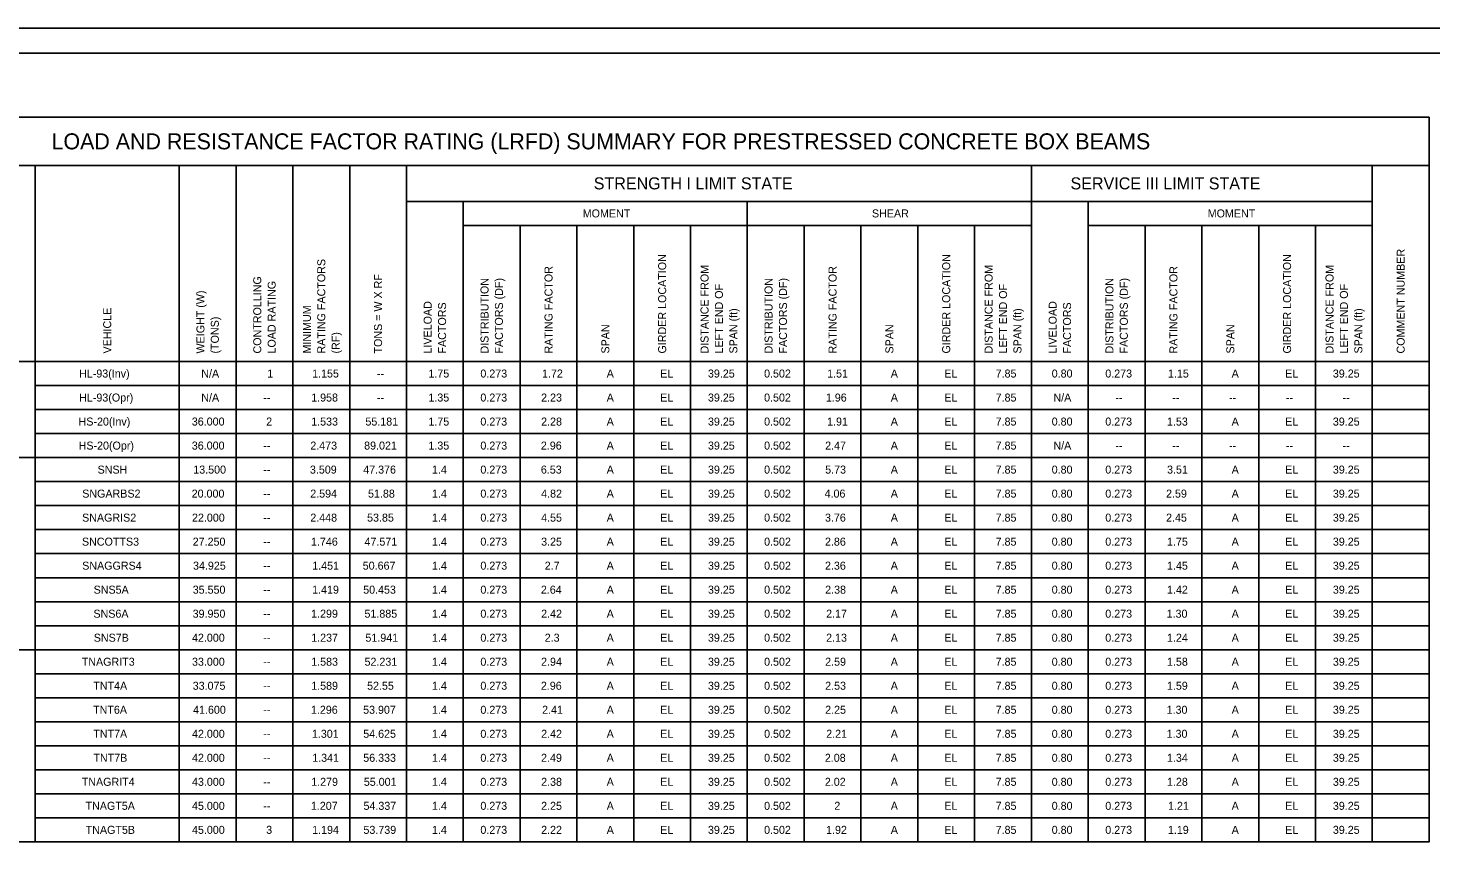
# Model space of a CAD drawing. Extents: x -190 to 360, y 729 to 1065.
# Drawn here: x 7.6 to 226.8, y 820.2 to 949.5 of the extents above; entities that cross this region are included whole.
import ezdxf

# ---------------------------------------------------------------- set-up
doc = ezdxf.new("R2010")
doc.units = 0
for name, color, linetype in [('Bill of Material Border Lines', 7, 'Continuous'), ('Bill of Material Lines', 7, 'Continuous'), ('Miscellaneous Lines', 7, 'Continuous'), ('Plan Sheet CELL', 7, 'Continuous'), ('Plot Shape CELL', 7, 'Continuous'), ('Text', 7, 'Continuous')]:
    doc.layers.add(name, color=color, linetype=linetype)

msp = doc.modelspace()

# ---------------------------------------------------------------- linework, layer by layer
at = {"layer": 'Bill of Material Border Lines'}
msp.add_lwpolyline([(-9.99, 935.55), (226.51, 935.55), (226.51, 822.42), (-9.99, 822.42), (-9.99, 935.55)], dxfattribs=at)
at = {"layer": 'Bill of Material Lines'}
for p, q in [((-9.99, 928.05), (226.51, 928.05)), ((8.76, 928.05), (8.76, 822.42)), ((31.26, 928.05), (31.26, 822.42)), ((40.14, 928.05), (40.14, 822.42)), ((49.01, 928.05), (49.01, 822.42)), ((57.89, 928.05), (57.89, 822.42)), ((66.76, 928.05), (66.76, 822.42)), ((164.39, 928.05), (164.39, 822.42)), ((217.64, 928.05), (217.64, 822.42)), ((226.51, 928.05), (226.51, 822.42)), ((66.76, 922.42), (217.64, 922.42)), ((75.64, 922.42), (75.64, 822.42)), ((120.01, 922.42), (120.01, 822.42)), ((173.26, 922.42), (173.26, 822.42)), ((75.64, 918.67), (164.39, 918.67)), ((84.51, 918.67), (84.51, 822.42)), ((93.39, 918.67), (93.39, 822.42)), ((102.26, 918.67), (102.26, 822.42)), ((111.14, 918.67), (111.14, 822.42)), ((128.89, 918.67), (128.89, 822.42)), ((137.76, 918.67), (137.76, 822.42)), ((146.64, 918.67), (146.64, 822.42)), ((155.51, 918.67), (155.51, 822.42)), ((173.26, 918.67), (217.64, 918.67)), ((182.14, 918.67), (182.14, 822.42)), ((191.01, 918.67), (191.01, 822.42)), ((199.89, 918.67), (199.89, 822.42)), ((208.76, 918.67), (208.76, 822.42)), ((-9.99, 897.42), (226.51, 897.42)), ((8.76, 893.67), (226.51, 893.67)), ((8.76, 889.92), (226.51, 889.92)), ((8.76, 886.17), (226.51, 886.17)), ((-9.99, 882.42), (226.51, 882.42)), ((8.76, 878.67), (226.51, 878.67)), ((8.76, 874.92), (226.51, 874.92)), ((8.76, 871.17), (226.51, 871.17)), ((8.76, 867.42), (226.51, 867.42)), ((8.76, 863.67), (226.51, 863.67)), ((8.76, 859.92), (226.51, 859.92)), ((8.76, 856.17), (226.51, 856.17)), ((2.64, 852.42), (226.51, 852.42)), ((8.76, 848.67), (226.51, 848.67)), ((8.76, 844.92), (226.51, 844.92)), ((8.76, 841.17), (226.51, 841.17)), ((8.76, 837.42), (226.51, 837.42)), ((8.76, 833.67), (226.51, 833.67)), ((8.76, 829.92), (226.51, 829.92)), ((8.76, 826.17), (226.51, 826.17))]:
    msp.add_line(p, q, dxfattribs=at)
at = {"layer": 'Plan Sheet CELL'}
msp.add_line((-16.76, 945.55), (303.24, 945.55), dxfattribs=at)
at = {"layer": 'Plot Shape CELL'}
msp.add_lwpolyline([(-27.3, 949.49), (303.33, 949.49), (303.33, 729.49), (-27.3, 729.49)], close=True, dxfattribs=at)

# ---------------------------------------------------------------- texts
at = {"layer": 'Miscellaneous Lines'}
for s, p in [('1', (45.01, 894.92)), ('1.15', (185.72, 894.92)), ('39.25', (211.48, 894.92)), ('2', (44.85, 887.42)), ('1.53', (185.57, 887.42)), ('39.25', (211.48, 887.42)), ('3', (44.85, 823.67)), ('1.19', (185.71, 823.67)), ('39.25', (211.48, 823.67))]:
    msp.add_text(s, height=1.25, dxfattribs=at).set_placement(p)
at = {"layer": 'Text'}
for s, height, p in [('LOAD AND RESISTANCE FACTOR RATING (LRFD) SUMMARY FOR PRESTRESSED CONCRETE BOX BEAMS', 2.5, (11.32, 930.55)), ('STRENGTH I LIMIT STATE', 1.875, (96.02, 924.3)), ('SERVICE III LIMIT STATE', 1.875, (170.5, 924.3)), ('MOMENT', 1.25, (94.3, 919.92)), ('SHEAR', 1.25, (139.48, 919.92)), ('MOMENT', 1.25, (191.93, 919.92)), ('HL-93(Inv)', 1.25, (15.62, 894.92)), ('N/A', 1.25, (34.71, 894.92)), ('1.155', 1.25, (52.03, 894.92)), ('--', 1.25, (62.14, 894.92)), ('1.75', 1.25, (70.19, 894.92)), ('0.273', 1.25, (78.31, 894.92)), ('1.72', 1.25, (87.94, 894.92)), ('A', 1.25, (98.04, 894.92)), ('EL', 1.25, (106.41, 894.92)), ('39.25', 1.25, (113.86, 894.92)), ('0.502', 1.25, (122.63, 894.92)), ('1.51', 1.25, (132.48, 894.92)), ('A', 1.25, (142.42, 894.92)), ('EL', 1.25, (150.78, 894.92)), ('7.85', 1.25, (158.8, 894.92)), ('0.80', 1.25, (167.56, 894.92)), ('0.273', 1.25, (175.93, 894.92)), ('A', 1.25, (195.67, 894.92)), ('EL', 1.25, (204.03, 894.92)), ('HL-93(Opr)', 1.25, (15.63, 891.17)), ('N/A', 1.25, (34.71, 891.17)), ('1.958', 1.25, (51.88, 891.17)), ('1.35', 1.25, (70.19, 891.17)), ('0.273', 1.25, (78.31, 891.17)), ('2.23', 1.25, (87.8, 891.17)), ('A', 1.25, (98.04, 891.17)), ('EL', 1.25, (106.41, 891.17)), ('39.25', 1.25, (113.86, 891.17)), ('0.502', 1.25, (122.63, 891.17)), ('1.96', 1.25, (132.28, 891.17)), ('A', 1.25, (142.42, 891.17)), ('EL', 1.25, (150.78, 891.17)), ('7.85', 1.25, (158.8, 891.17)), ('N/A', 1.25, (167.83, 891.17)), ('--', 1.25, (44.39, 891.17)), ('--', 1.25, (62.14, 891.17)), ('--', 1.25, (177.51, 891.17)), ('--', 1.25, (186.39, 891.17)), ('--', 1.25, (195.26, 891.17)), ('--', 1.25, (204.14, 891.17)), ('--', 1.25, (213.01, 891.17)), ('HS-20(Inv)', 1.25, (15.54, 887.42)), ('36.000', 1.25, (33.23, 887.42)), ('1.533', 1.25, (51.88, 887.42)), ('55.181', 1.25, (60.35, 887.42)), ('1.75', 1.25, (70.19, 887.42)), ('0.273', 1.25, (78.31, 887.42)), ('2.28', 1.25, (87.8, 887.42)), ('A', 1.25, (98.04, 887.42)), ('EL', 1.25, (106.41, 887.42)), ('39.25', 1.25, (113.86, 887.42)), ('0.502', 1.25, (122.63, 887.42)), ('1.91', 1.25, (132.47, 887.42)), ('A', 1.25, (142.42, 887.42)), ('EL', 1.25, (150.78, 887.42)), ('7.85', 1.25, (158.8, 887.42)), ('0.80', 1.25, (167.56, 887.42)), ('0.273', 1.25, (175.93, 887.42)), ('A', 1.25, (195.67, 887.42)), ('EL', 1.25, (204.03, 887.42)), ('HS-20(Opr)', 1.25, (15.55, 883.67)), ('36.000', 1.25, (33.23, 883.67)), ('--', 1.25, (44.39, 883.67)), ('2.473', 1.25, (51.74, 883.67)), ('89.021', 1.25, (60.15, 883.67)), ('1.35', 1.25, (70.19, 883.67)), ('0.273', 1.25, (78.31, 883.67)), ('2.96', 1.25, (87.76, 883.67)), ('A', 1.25, (98.04, 883.67)), ('EL', 1.25, (106.41, 883.67)), ('39.25', 1.25, (113.86, 883.67)), ('0.502', 1.25, (122.63, 883.67)), ('2.47', 1.25, (132.17, 883.67)), ('A', 1.25, (142.42, 883.67)), ('EL', 1.25, (150.78, 883.67)), ('7.85', 1.25, (158.8, 883.67)), ('N/A', 1.25, (167.83, 883.67)), ('--', 1.25, (177.51, 883.67)), ('--', 1.25, (186.39, 883.67)), ('--', 1.25, (195.26, 883.67)), ('--', 1.25, (204.14, 883.67)), ('--', 1.25, (213.01, 883.67)), ('SNSH', 1.25, (18.51, 879.92)), ('13.500', 1.25, (33.46, 879.92)), ('3.509', 1.25, (51.68, 879.92)), ('47.376', 1.25, (60.01, 879.92)), ('1.4', 1.25, (70.75, 879.92)), ('0.273', 1.25, (78.31, 879.92)), ('6.53', 1.25, (87.76, 879.92)), ('A', 1.25, (98.04, 879.92)), ('EL', 1.25, (106.41, 879.92)), ('39.25', 1.25, (113.86, 879.92)), ('0.502', 1.25, (122.63, 879.92)), ('5.73', 1.25, (132.17, 879.92)), ('A', 1.25, (142.42, 879.92)), ('EL', 1.25, (150.78, 879.92)), ('7.85', 1.25, (158.8, 879.92)), ('0.80', 1.25, (167.56, 879.92)), ('0.273', 1.25, (175.93, 879.92)), ('3.51', 1.25, (185.58, 879.92)), ('A', 1.25, (195.67, 879.92)), ('EL', 1.25, (204.03, 879.92)), ('39.25', 1.25, (211.48, 879.92)), ('--', 1.25, (44.39, 879.92)), ('SNGARBS2', 1.25, (16.11, 876.17)), ('20.000', 1.25, (33.21, 876.17)), ('--', 1.25, (44.39, 876.17)), ('2.594', 1.25, (51.73, 876.17)), ('51.88', 1.25, (60.76, 876.17)), ('1.4', 1.25, (70.75, 876.17)), ('0.273', 1.25, (78.31, 876.17)), ('4.82', 1.25, (87.8, 876.17)), ('A', 1.25, (98.04, 876.17)), ('EL', 1.25, (106.41, 876.17)), ('39.25', 1.25, (113.86, 876.17)), ('0.502', 1.25, (122.63, 876.17)), ('4.06', 1.25, (132.08, 876.17)), ('A', 1.25, (142.42, 876.17)), ('EL', 1.25, (150.78, 876.17)), ('7.85', 1.25, (158.8, 876.17)), ('0.80', 1.25, (167.56, 876.17)), ('0.273', 1.25, (175.93, 876.17)), ('2.59', 1.25, (185.42, 876.17)), ('A', 1.25, (195.67, 876.17)), ('EL', 1.25, (204.03, 876.17)), ('39.25', 1.25, (211.48, 876.17)), ('SNAGRIS2', 1.25, (16.09, 872.42)), ('22.000', 1.25, (33.26, 872.42)), ('--', 1.25, (44.39, 872.42)), ('2.448', 1.25, (51.74, 872.42)), ('53.85', 1.25, (60.61, 872.42)), ('1.4', 1.25, (70.75, 872.42)), ('0.273', 1.25, (78.31, 872.42)), ('4.55', 1.25, (87.8, 872.42)), ('A', 1.25, (98.04, 872.42)), ('EL', 1.25, (106.41, 872.42)), ('39.25', 1.25, (113.86, 872.42)), ('0.502', 1.25, (122.63, 872.42)), ('3.76', 1.25, (132.14, 872.42)), ('A', 1.25, (142.42, 872.42)), ('EL', 1.25, (150.78, 872.42)), ('7.85', 1.25, (158.8, 872.42)), ('0.80', 1.25, (167.56, 872.42)), ('0.273', 1.25, (175.93, 872.42)), ('2.45', 1.25, (185.42, 872.42)), ('A', 1.25, (195.67, 872.42)), ('EL', 1.25, (204.03, 872.42)), ('39.25', 1.25, (211.48, 872.42)), ('SNCOTTS3', 1.25, (16.07, 868.67)), ('27.250', 1.25, (33.37, 868.67)), ('--', 1.25, (44.39, 868.67)), ('1.746', 1.25, (51.85, 868.67)), ('47.571', 1.25, (60.21, 868.67)), ('1.4', 1.25, (70.75, 868.67)), ('0.273', 1.25, (78.31, 868.67)), ('3.25', 1.25, (87.8, 868.67)), ('A', 1.25, (98.04, 868.67)), ('EL', 1.25, (106.41, 868.67)), ('39.25', 1.25, (113.86, 868.67)), ('0.502', 1.25, (122.63, 868.67)), ('2.86', 1.25, (132.14, 868.67)), ('A', 1.25, (142.42, 868.67)), ('EL', 1.25, (150.78, 868.67)), ('7.85', 1.25, (158.8, 868.67)), ('0.80', 1.25, (167.56, 868.67)), ('0.273', 1.25, (175.93, 868.67)), ('1.75', 1.25, (185.57, 868.67)), ('A', 1.25, (195.67, 868.67)), ('EL', 1.25, (204.03, 868.67)), ('39.25', 1.25, (211.48, 868.67)), ('SNAGGRS4', 1.25, (16.11, 864.92)), ('34.925', 1.25, (33.42, 864.92)), ('1.451', 1.25, (52.04, 864.92)), ('50.667', 1.25, (59.93, 864.92)), ('1.4', 1.25, (70.75, 864.92)), ('0.273', 1.25, (78.31, 864.92)), ('2.7', 1.25, (88.36, 864.92)), ('A', 1.25, (98.04, 864.92)), ('EL', 1.25, (106.41, 864.92)), ('39.25', 1.25, (113.86, 864.92)), ('0.502', 1.25, (122.63, 864.92)), ('2.36', 1.25, (132.14, 864.92)), ('A', 1.25, (142.42, 864.92)), ('EL', 1.25, (150.78, 864.92)), ('7.85', 1.25, (158.8, 864.92)), ('0.80', 1.25, (167.56, 864.92)), ('0.273', 1.25, (175.93, 864.92)), ('1.45', 1.25, (185.57, 864.92)), ('A', 1.25, (195.67, 864.92)), ('EL', 1.25, (204.03, 864.92)), ('39.25', 1.25, (211.48, 864.92)), ('--', 1.25, (44.39, 864.92)), ('SNS5A', 1.25, (17.89, 861.17)), ('35.550', 1.25, (33.37, 861.17)), ('--', 1.25, (44.39, 861.17)), ('1.419', 1.25, (52.03, 861.17)), ('50.453', 1.25, (60, 861.17)), ('1.4', 1.25, (70.75, 861.17)), ('0.273', 1.25, (78.31, 861.17)), ('2.64', 1.25, (87.76, 861.17)), ('A', 1.25, (98.04, 861.17)), ('EL', 1.25, (106.41, 861.17)), ('39.25', 1.25, (113.86, 861.17)), ('0.502', 1.25, (122.63, 861.17)), ('2.38', 1.25, (132.17, 861.17)), ('A', 1.25, (142.42, 861.17)), ('EL', 1.25, (150.78, 861.17)), ('7.85', 1.25, (158.8, 861.17)), ('0.80', 1.25, (167.56, 861.17)), ('0.273', 1.25, (175.93, 861.17)), ('1.42', 1.25, (185.57, 861.17)), ('A', 1.25, (195.67, 861.17)), ('EL', 1.25, (204.03, 861.17)), ('39.25', 1.25, (211.48, 861.17)), ('SNS6A', 1.25, (17.86, 857.42)), ('39.950', 1.25, (33.36, 857.42)), ('--', 1.25, (44.39, 857.42)), ('1.299', 1.25, (51.87, 857.42)), ('51.885', 1.25, (60.2, 857.42)), ('1.4', 1.25, (70.75, 857.42)), ('0.273', 1.25, (78.31, 857.42)), ('2.42', 1.25, (87.8, 857.42)), ('A', 1.25, (98.04, 857.42)), ('EL', 1.25, (106.41, 857.42)), ('39.25', 1.25, (113.86, 857.42)), ('0.502', 1.25, (122.63, 857.42)), ('2.17', 1.25, (132.32, 857.42)), ('A', 1.25, (142.42, 857.42)), ('EL', 1.25, (150.78, 857.42)), ('7.85', 1.25, (158.8, 857.42)), ('0.80', 1.25, (167.56, 857.42)), ('0.273', 1.25, (175.93, 857.42)), ('1.30', 1.25, (185.51, 857.42)), ('A', 1.25, (195.67, 857.42)), ('EL', 1.25, (204.03, 857.42)), ('39.25', 1.25, (211.48, 857.42)), ('SNS7B', 1.25, (17.91, 853.67)), ('42.000', 1.25, (33.26, 853.67)), ('1.237', 1.25, (51.88, 853.67)), ('51.941', 1.25, (60.35, 853.67)), ('1.4', 1.25, (70.75, 853.67)), ('0.273', 1.25, (78.31, 853.67)), ('2.3', 1.25, (88.36, 853.67)), ('A', 1.25, (98.04, 853.67)), ('EL', 1.25, (106.41, 853.67)), ('39.25', 1.25, (113.86, 853.67)), ('0.502', 1.25, (122.63, 853.67)), ('2.13', 1.25, (132.32, 853.67)), ('A', 1.25, (142.42, 853.67)), ('EL', 1.25, (150.78, 853.67)), ('7.85', 1.25, (158.8, 853.67)), ('0.80', 1.25, (167.56, 853.67)), ('0.273', 1.25, (175.93, 853.67)), ('1.24', 1.25, (185.57, 853.67)), ('A', 1.25, (195.67, 853.67)), ('EL', 1.25, (204.03, 853.67)), ('39.25', 1.25, (211.48, 853.67)), ('--', 1.25, (44.39, 853.67)), ('TNAGRIT3', 1.25, (16.04, 849.92)), ('33.000', 1.25, (33.26, 849.92)), ('--', 1.25, (44.39, 849.92)), ('1.583', 1.25, (51.88, 849.92)), ('52.231', 1.25, (60.21, 849.92)), ('1.4', 1.25, (70.75, 849.92)), ('0.273', 1.25, (78.31, 849.92)), ('2.94', 1.25, (87.79, 849.92)), ('A', 1.25, (98.04, 849.92)), ('EL', 1.25, (106.41, 849.92)), ('39.25', 1.25, (113.86, 849.92)), ('0.502', 1.25, (122.63, 849.92)), ('2.59', 1.25, (132.17, 849.92)), ('A', 1.25, (142.42, 849.92)), ('EL', 1.25, (150.78, 849.92)), ('7.85', 1.25, (158.8, 849.92)), ('0.80', 1.25, (167.56, 849.92)), ('0.273', 1.25, (175.93, 849.92)), ('1.58', 1.25, (185.57, 849.92)), ('A', 1.25, (195.67, 849.92)), ('EL', 1.25, (204.03, 849.92)), ('39.25', 1.25, (211.48, 849.92)), ('TNT4A', 1.25, (17.84, 846.17)), ('33.075', 1.25, (33.37, 846.17)), ('--', 1.25, (44.39, 846.17)), ('1.589', 1.25, (51.88, 846.17)), ('52.55', 1.25, (60.61, 846.17)), ('1.4', 1.25, (70.75, 846.17)), ('0.273', 1.25, (78.31, 846.17)), ('2.96', 1.25, (87.76, 846.17)), ('A', 1.25, (98.04, 846.17)), ('EL', 1.25, (106.41, 846.17)), ('39.25', 1.25, (113.86, 846.17)), ('0.502', 1.25, (122.63, 846.17)), ('2.53', 1.25, (132.17, 846.17)), ('A', 1.25, (142.42, 846.17)), ('EL', 1.25, (150.78, 846.17)), ('7.85', 1.25, (158.8, 846.17)), ('0.80', 1.25, (167.56, 846.17)), ('0.273', 1.25, (175.93, 846.17)), ('1.59', 1.25, (185.56, 846.17)), ('A', 1.25, (195.67, 846.17)), ('EL', 1.25, (204.03, 846.17)), ('39.25', 1.25, (211.48, 846.17)), ('TNT6A', 1.25, (17.81, 842.42)), ('41.600', 1.25, (33.43, 842.42)), ('--', 1.25, (44.39, 842.42)), ('1.296', 1.25, (51.84, 842.42)), ('53.907', 1.25, (59.99, 842.42)), ('1.4', 1.25, (70.75, 842.42)), ('0.273', 1.25, (78.31, 842.42)), ('2.41', 1.25, (87.95, 842.42)), ('A', 1.25, (98.04, 842.42)), ('EL', 1.25, (106.41, 842.42)), ('39.25', 1.25, (113.86, 842.42)), ('0.502', 1.25, (122.63, 842.42)), ('2.25', 1.25, (132.17, 842.42)), ('A', 1.25, (142.42, 842.42)), ('EL', 1.25, (150.78, 842.42)), ('7.85', 1.25, (158.8, 842.42)), ('0.80', 1.25, (167.56, 842.42)), ('0.273', 1.25, (175.93, 842.42)), ('1.30', 1.25, (185.51, 842.42)), ('A', 1.25, (195.67, 842.42)), ('EL', 1.25, (204.03, 842.42)), ('39.25', 1.25, (211.48, 842.42)), ('TNT7A', 1.25, (17.84, 838.67)), ('42.000', 1.25, (33.26, 838.67)), ('1.301', 1.25, (51.99, 838.67)), ('54.625', 1.25, (60.01, 838.67)), ('1.4', 1.25, (70.75, 838.67)), ('0.273', 1.25, (78.31, 838.67)), ('2.42', 1.25, (87.8, 838.67)), ('A', 1.25, (98.04, 838.67)), ('EL', 1.25, (106.41, 838.67)), ('39.25', 1.25, (113.86, 838.67)), ('0.502', 1.25, (122.63, 838.67)), ('2.21', 1.25, (132.33, 838.67)), ('A', 1.25, (142.42, 838.67)), ('EL', 1.25, (150.78, 838.67)), ('7.85', 1.25, (158.8, 838.67)), ('0.80', 1.25, (167.56, 838.67)), ('0.273', 1.25, (175.93, 838.67)), ('1.30', 1.25, (185.51, 838.67)), ('A', 1.25, (195.67, 838.67)), ('EL', 1.25, (204.03, 838.67)), ('39.25', 1.25, (211.48, 838.67)), ('--', 1.25, (44.39, 838.67)), ('TNT7B', 1.25, (17.86, 834.92)), ('42.000', 1.25, (33.26, 834.92)), ('--', 1.25, (44.39, 834.92)), ('1.341', 1.25, (52.04, 834.92)), ('56.333', 1.25, (60.01, 834.92)), ('1.4', 1.25, (70.75, 834.92)), ('0.273', 1.25, (78.31, 834.92)), ('2.49', 1.25, (87.79, 834.92)), ('A', 1.25, (98.04, 834.92)), ('EL', 1.25, (106.41, 834.92)), ('39.25', 1.25, (113.86, 834.92)), ('0.502', 1.25, (122.63, 834.92)), ('2.08', 1.25, (132.12, 834.92)), ('A', 1.25, (142.42, 834.92)), ('EL', 1.25, (150.78, 834.92)), ('7.85', 1.25, (158.8, 834.92)), ('0.80', 1.25, (167.56, 834.92)), ('0.273', 1.25, (175.93, 834.92)), ('1.34', 1.25, (185.57, 834.92)), ('A', 1.25, (195.67, 834.92)), ('EL', 1.25, (204.03, 834.92)), ('39.25', 1.25, (211.48, 834.92)), ('TNAGRIT4', 1.25, (16.04, 831.17)), ('43.000', 1.25, (33.26, 831.17)), ('--', 1.25, (44.39, 831.17)), ('1.279', 1.25, (51.88, 831.17)), ('55.001', 1.25, (60.1, 831.17)), ('1.4', 1.25, (70.75, 831.17)), ('0.273', 1.25, (78.31, 831.17)), ('2.38', 1.25, (87.8, 831.17)), ('A', 1.25, (98.04, 831.17)), ('EL', 1.25, (106.41, 831.17)), ('39.25', 1.25, (113.86, 831.17)), ('0.502', 1.25, (122.63, 831.17)), ('2.02', 1.25, (132.12, 831.17)), ('A', 1.25, (142.42, 831.17)), ('EL', 1.25, (150.78, 831.17)), ('7.85', 1.25, (158.8, 831.17)), ('0.80', 1.25, (167.56, 831.17)), ('0.273', 1.25, (175.93, 831.17)), ('1.28', 1.25, (185.57, 831.17)), ('A', 1.25, (195.67, 831.17)), ('EL', 1.25, (204.03, 831.17)), ('39.25', 1.25, (211.48, 831.17)), ('TNAGT5A', 1.25, (16.63, 827.42)), ('45.000', 1.25, (33.26, 827.42)), ('1.207', 1.25, (51.83, 827.42)), ('54.337', 1.25, (60.05, 827.42)), ('1.4', 1.25, (70.75, 827.42)), ('0.273', 1.25, (78.31, 827.42)), ('2.25', 1.25, (87.8, 827.42)), ('A', 1.25, (98.04, 827.42)), ('EL', 1.25, (106.41, 827.42)), ('39.25', 1.25, (113.86, 827.42)), ('0.502', 1.25, (122.63, 827.42)), ('2', 1.25, (133.6, 827.42)), ('A', 1.25, (142.42, 827.42)), ('EL', 1.25, (150.78, 827.42)), ('7.85', 1.25, (158.8, 827.42)), ('0.80', 1.25, (167.56, 827.42)), ('0.273', 1.25, (175.93, 827.42)), ('1.21', 1.25, (185.73, 827.42)), ('A', 1.25, (195.67, 827.42)), ('EL', 1.25, (204.03, 827.42)), ('39.25', 1.25, (211.48, 827.42)), ('--', 1.25, (44.39, 827.42)), ('TNAGT5B', 1.25, (16.65, 823.67)), ('45.000', 1.25, (33.26, 823.67)), ('1.194', 1.25, (52.03, 823.67)), ('53.739', 1.25, (60.04, 823.67)), ('1.4', 1.25, (70.75, 823.67)), ('0.273', 1.25, (78.31, 823.67)), ('2.22', 1.25, (87.8, 823.67)), ('A', 1.25, (98.04, 823.67)), ('EL', 1.25, (106.41, 823.67)), ('39.25', 1.25, (113.86, 823.67)), ('0.502', 1.25, (122.63, 823.67)), ('1.92', 1.25, (132.31, 823.67)), ('A', 1.25, (142.42, 823.67)), ('EL', 1.25, (150.78, 823.67)), ('7.85', 1.25, (158.8, 823.67)), ('0.80', 1.25, (167.56, 823.67)), ('0.273', 1.25, (175.93, 823.67)), ('A', 1.25, (195.67, 823.67)), ('EL', 1.25, (204.03, 823.67))]:
    msp.add_text(s, height=height, dxfattribs=at).set_placement(p)
for s, p in [('GIRDER LOCATION', (107.33, 898.67)), ('GIRDER LOCATION', (151.7, 898.67)), ('GIRDER LOCATION', (204.95, 898.67)), ('COMMENT NUMBER', (222.7, 898.67)), ('RATING FACTORS', (54.08, 898.67)), ('RATING FACTOR ', (89.58, 898.67)), ('DISTANCE FROM', (113.95, 898.67)), ('RATING FACTOR ', (133.95, 898.67)), ('DISTANCE FROM', (158.33, 898.67)), ('RATING FACTOR', (187.2, 898.67)), ('DISTANCE FROM', (211.58, 898.67)), ('CONTROLLING ', (44.08, 898.67)), ('LOAD RATING ', (46.33, 898.67)), ('TONS = W X RF ', (62.95, 898.67)), ('DISTRIBUTION', (79.58, 898.67)), ('FACTORS (DF)', (81.83, 898.67)), ('DISTRIBUTION', (123.95, 898.67)), ('FACTORS (DF)', (126.2, 898.67)), ('DISTRIBUTION', (177.2, 898.67)), ('FACTORS (DF)', (179.45, 898.67)), ('WEIGHT (W) ', (35.2, 898.67)), ('LEFT END OF', (116.2, 898.67)), ('LEFT END OF', (160.58, 898.67)), ('LEFT END OF', (213.83, 898.67)), ('VEHICLE', (20.64, 898.67)), ('MINIMUM', (51.83, 898.67)), ('LIVELOAD', (70.7, 898.67)), ('FACTORS ', (72.95, 898.67)), ('SPAN (ft)', (118.45, 898.67)), ('SPAN (ft)', (162.83, 898.67)), ('LIVELOAD', (168.33, 898.67)), ('FACTORS ', (170.58, 898.67)), ('SPAN (ft)', (216.08, 898.67)), ('(TONS) ', (37.45, 898.67)), ('SPAN', (98.45, 898.67)), ('SPAN ', (142.83, 898.67)), ('SPAN', (196.08, 898.67)), ('(RF)', (56.33, 898.67))]:
    msp.add_text(s, height=1.25, rotation=90, dxfattribs=at).set_placement(p)

doc.saveas('drawing.dxf')
